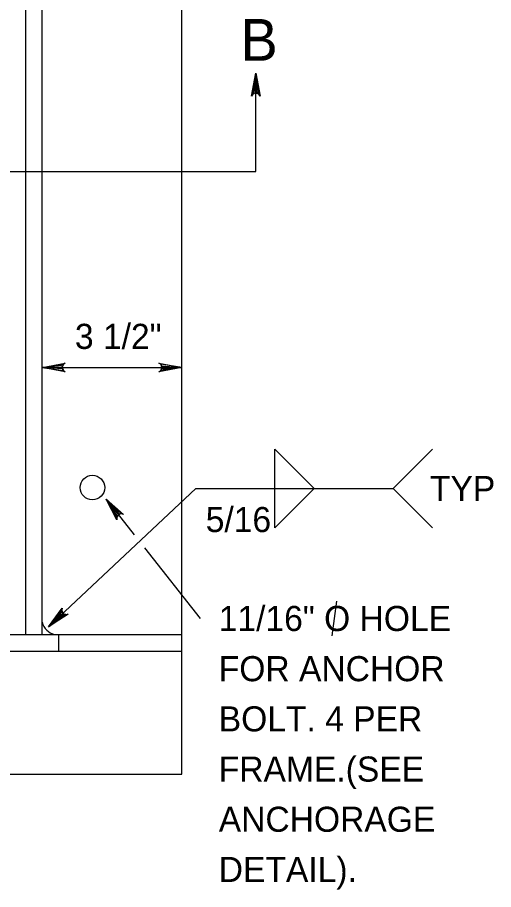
# Model space of a CAD drawing. Extents: x 0.71 to 8.05, y -5.67 to 4.31.
# Drawn here: x 6.63 to 7.767, y 0.27 to 2.355 of the extents above; entities that cross this region are included whole.
import ezdxf

# ---------------------------------------------------------------- set-up
doc = ezdxf.new("R2010")
doc.units = 0
for name, color, linetype in [('DETL-DIMS', 7, 'Continuous'), ('DETL-LINE', 7, 'Continuous'), ('DETL-NOTE', 7, 'Continuous'), ('DETL-TITL', 7, 'Continuous')]:
    doc.layers.add(name, color=color, linetype=linetype)

msp = doc.modelspace()

# ---------------------------------------------------------------- linework, layer by layer
at = {"layer": 'DETL-DIMS'}
for p, q in [((7.1992, 1.9865), (7.1992, 2.2218)), ((6.345, 1.9865), (7.1992, 1.9865)), ((6.6892, 1.5183), (7.0228, 1.5183)), ((7.0562, 1.2286), (6.7041, 0.898)), ((6.8416, 1.2031), (6.9088, 1.118)), ((6.9336, 1.0865), (7.0666, 0.918))]:
    msp.add_line(p, q, dxfattribs=at)
for points in [[(7.1992, 2.2218), (7.2095, 2.167), (7.2066, 2.1712), (7.2029, 2.1734), (7.1992, 2.174), (7.1956, 2.1734), (7.1919, 2.1712), (7.1889, 2.167), (7.1992, 2.2218), (7.1919, 2.1712), (7.1956, 2.1734), (7.1992, 2.2218), (7.1992, 2.174), (7.2029, 2.1734), (7.1992, 2.2218), (7.2066, 2.1712)], [(6.6892, 1.5183), (6.7441, 1.5286), (6.7398, 1.5256), (6.7377, 1.522), (6.737, 1.5183), (6.7377, 1.5146), (6.7398, 1.5109), (6.7441, 1.508), (6.6892, 1.5183), (6.7398, 1.5109), (6.7377, 1.5146), (6.6892, 1.5183), (6.737, 1.5183), (6.7377, 1.522), (6.6892, 1.5183), (6.7398, 1.5256)], [(7.0228, 1.5183), (6.9679, 1.508), (6.9722, 1.5109), (6.9743, 1.5146), (6.975, 1.5183), (6.9743, 1.522), (6.9722, 1.5256), (6.9679, 1.5286), (7.0228, 1.5183), (6.9722, 1.5256), (6.9743, 1.522), (7.0228, 1.5183), (6.975, 1.5183), (6.9743, 1.5146), (7.0228, 1.5183), (6.9722, 1.5109)], [(7.0562, 1.2286), (7.3386, 1.2286), (7.2444, 1.1345), (7.2444, 1.3227), (7.3386, 1.2286), (7.5268, 1.2286)], [(7.6209, 1.3227), (7.5268, 1.2286), (7.6209, 1.1345)], [(6.8416, 1.2031), (6.8836, 1.1665), (6.8787, 1.168), (6.8745, 1.1674), (6.8712, 1.1656), (6.8687, 1.1628), (6.8672, 1.1589), (6.8675, 1.1537), (6.8416, 1.2031), (6.8672, 1.1589), (6.8687, 1.1628), (6.8416, 1.2031), (6.8712, 1.1656), (6.8745, 1.1674), (6.8416, 1.2031), (6.8787, 1.168)], [(6.7041, 0.898), (6.737, 0.943), (6.736, 0.938), (6.7369, 0.9338), (6.7389, 0.9307), (6.7419, 0.9284), (6.746, 0.9272), (6.7511, 0.928), (6.7041, 0.898), (6.746, 0.9272), (6.7419, 0.9284), (6.7041, 0.898), (6.7389, 0.9307), (6.7369, 0.9338), (6.7041, 0.898), (6.736, 0.938)]]:
    msp.add_lwpolyline(points, dxfattribs=at)
at = {"layer": 'DETL-LINE'}
for p, q in [((7.0228, 0.546), (7.0228, 3.2036)), ((6.6498, 0.8795), (6.6498, 2.8701)), ((6.6892, 0.8795), (6.6892, 2.8701)), ((2.1992, 0.8795), (7.0228, 0.8795)), ((6.7286, 0.8401), (6.7286, 0.8795)), ((2.1992, 0.8401), (7.0228, 0.8401)), ((2.1992, 0.546), (7.0228, 0.546))]:
    msp.add_line(p, q, dxfattribs=at)
msp.add_circle((6.8091, 1.2309), 0.0294, dxfattribs=at)
msp.add_arc((6.7287, 0.9189), 0.0407, 194.2782, 255.7218, dxfattribs=at)
at = {"layer": 'DETL-NOTE'}
msp.add_line((7.3918, 0.9593), (7.3811, 0.8767), dxfattribs=at)

# ---------------------------------------------------------------- texts
for s, p in [('3 1/2"', (6.7673, 1.5624)), ('TYP', (7.615, 1.1986)), ('5/16', (7.0796, 1.1245)), ('11/16" O HOLE', (7.1107, 0.888)), ('FOR ANCHOR', (7.1107, 0.768)), ('BOLT. 4 PER', (7.1107, 0.648)), ('FRAME.(SEE ', (7.1107, 0.528)), ('ANCHORAGE', (7.1107, 0.408)), ('DETAIL).', (7.1107, 0.288))]:
    msp.add_text(s, height=0.06, dxfattribs=at).set_placement(p)
at = {"layer": 'DETL-TITL'}
msp.add_text('B', height=0.1, dxfattribs=at).set_placement((7.1625, 2.2512))

doc.saveas('drawing.dxf')
